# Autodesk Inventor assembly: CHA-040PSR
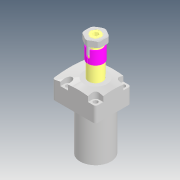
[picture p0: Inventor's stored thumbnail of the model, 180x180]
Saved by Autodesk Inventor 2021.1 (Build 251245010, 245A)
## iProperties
Created: 2018-12
Part Number: CHA-040PSR
Description: STEP AP214
Document SubType Name: Assembly
Designer: user
Title: CHA-040PSR.STEP
Revision Number: ÈÎºÎ
Sending System: SolidWorks 2016
Preprocessor: SwSTEP 2.0
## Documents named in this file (7)
- D:\Vault_2016\Projekty\Clamptek\Hydraulic\CHA-P\Inventor\CHA-040PSR\CHA-040PSR.iam
- D:\Vault_2016\Projekty\Clamptek\Hydraulic\CHA-P\Inventor\CHA-040PSR\CHA-040P(BT).ipt
- D:\Vault_2016\Projekty\Clamptek\Hydraulic\CHA-P\Inventor\CHA-040PSR\¶ÂÍ·G8-1.ipt
- D:\Vault_2016\Projekty\Clamptek\Hydraulic\CHA-P\Inventor\CHA-040PSR\CHA-040PS×¶Ì×.ipt
- D:\Vault_2016\Projekty\Clamptek\Hydraulic\CHA-P\Inventor\CHA-040PSR\4x10.5(xiao).ipt
- D:\Vault_2016\Projekty\Clamptek\Hydraulic\CHA-P\Inventor\CHA-040PSR\M14x1.5LM.ipt
- D:\Vault_2016\Projekty\Clamptek\Hydraulic\CHA-P\Inventor\CHA-040PSR\CHA-040PS»îÈû¸Ë.ipt
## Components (7 placed, 7 different names)
1. CHA-040P(BT)_1
2. ¶ÂÍ·G8-1_2
3. CHA-040PS×¶Ì×_3
4. 4x10.5(xiao)_4
5. M14x1.5LM_5
6. ¶ÂÍ·G8-1_6
7. CHA-040PS»îÈû¸Ë_7
